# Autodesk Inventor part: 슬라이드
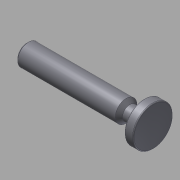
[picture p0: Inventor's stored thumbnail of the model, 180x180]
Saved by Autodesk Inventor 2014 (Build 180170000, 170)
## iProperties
Company: 한국ATC센터
Created: 2015-12
Part Number: 슬라이드
Document SubType Name: Modeling
Designer: mdu
Density: 7.86 g/cm^3
Mass: 68.0563 g
Surface Area: 34.7349 cm^2
Volume: 8.65856 cm^3
Material: 강철, 연강
Appearance: 강철
Author: mdu
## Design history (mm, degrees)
sketch "스케치1"
  geometry: L1 (-35, 0)-(35, 0); L2 (35, 0)-(35, 11); L3 (35, 11)-(30, 11); L4 (30, 11)-(30, 4); L5 (30, 4)-(22, 4); L6 (22, 4)-(20, 6); L7 (20, 6)-(-35, 6); L8 (-35, 6)-(-35, 0); 1 further point
  constraints: 16 end point, 4 parallel, 2 midpoint, 2 perpendicular, 1 horizontal
  dimensions: "d0" = 70 distance of L1.start L1.end; "d1" = 12 diameter of L7 L1; "d2" = 22 diameter of L3 L1; "d3" = 5 distance of L2.end L3.end; "d4" = 8 diameter of L5 L1; "d5" = 135 deg angle of L6 L5; "d6" = 15 distance from line of L2 L6.end
revolve "회전1" sketch "스케치1" stored, may be unused: angle "d7" = 90 deg
chamfer "모따기1" distance "d8" = 1; stored, may be unused: second distance "d9" = 2, angle "d10" = 45 deg
fillet "모깎기1" dims "d11" = 0.5
node "솔리드1"
